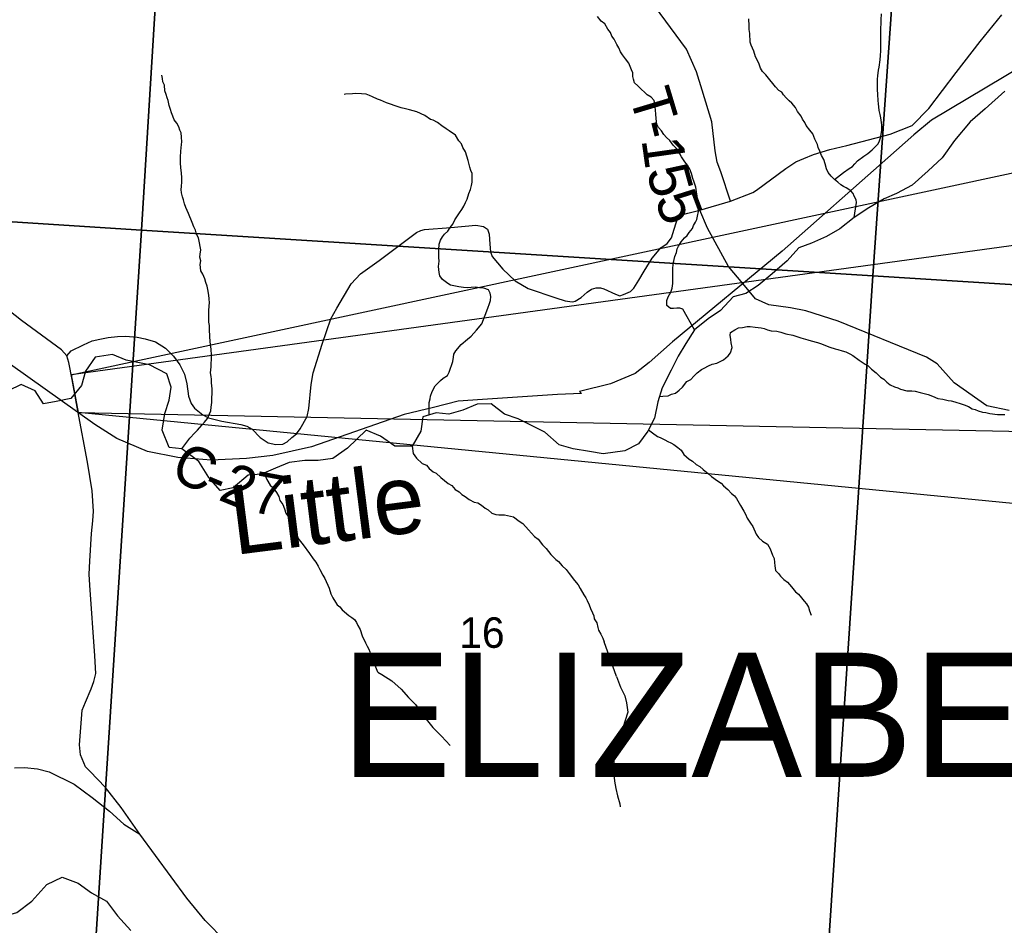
# Model space of a CAD drawing. Extents: x 0 to 44, y -23.8 to 22.
# Drawn here: x 5.27 to 6.622, y 16.572 to 17.815 of the extents above; entities that cross this region are included whole.
import ezdxf

# ---------------------------------------------------------------- set-up
doc = ezdxf.new("R2010")
doc.units = 0
for name, color, linetype in [('Default', 7, 'Continuous'), ('GM_X_County_Road', 7, 'Continuous'), ('GM_X_County_Road_Text', 7, 'Continuous'), ('GM_X_Minor_River', 7, 'Continuous'), ('GM_X_Minor_River_Text', 7, 'Continuous'), ('GM_X_Rail_Line', 7, 'Continuous'), ('GM_X_Section', 7, 'Continuous'), ('GM_X_Section_Text', 7, 'Continuous'), ('GM_X_State_Route', 7, 'Continuous'), ('GM_X_Township_Road', 7, 'Continuous'), ('GM_X_Township_Road_Text', 7, 'Continuous'), ('GM_X_Township_Text', 7, 'Continuous'), ('SH_Data', 7, 'Continuous')]:
    doc.layers.add(name, color=color, linetype=linetype)

msp = doc.modelspace()

# ---------------------------------------------------------------- linework, layer by layer
at = {"layer": 'Default'}
msp.add_line((5.3413, 17.3275), (5.3505, 17.2755), dxfattribs=at)
at = {"layer": 'GM_X_County_Road'}
msp.add_line((6.204, 17.5534), (6.2464, 17.5658), dxfattribs=at)
for points in [[(6.2464, 17.5658), (6.2769, 17.5775), (6.2822, 17.5808), (6.3221, 17.6107), (6.3361, 17.6195), (6.347, 17.6243), (6.3602, 17.6298), (6.3828, 17.6364), (6.4059, 17.6423), (6.4656, 17.6575), (6.4956, 17.6694), (6.5186, 17.6928), (6.5561, 17.7425), (6.5891, 17.785), (6.6186, 17.8214)], [(5.3353, 17.3535), (5.3413, 17.3604), (5.3582, 17.3685), (5.3701, 17.3739), (5.3805, 17.3765), (5.3918, 17.3785), (5.4047, 17.38), (5.416, 17.3805), (5.4316, 17.379), (5.4425, 17.3767), (5.4568, 17.3725), (5.4705, 17.364), (5.4814, 17.3528), (5.4904, 17.3411), (5.4969, 17.3285), (5.5001, 17.3148), (5.5024, 17.2981), (5.5057, 17.2881), (5.5106, 17.2814), (5.5218, 17.2726), (5.5297, 17.2682), (5.5481, 17.2638), (5.5742, 17.2591), (5.5821, 17.2568), (5.5894, 17.2527), (5.6005, 17.2415), (5.6114, 17.2342), (5.6219, 17.2316), (5.6316, 17.2322), (5.6377, 17.2354), (5.6439, 17.2412), (5.6503, 17.2465), (5.6553, 17.2533), (5.665, 17.2702), (5.6676, 17.2811), (5.6708, 17.3139), (5.6732, 17.3303), (5.6857, 17.3694), (5.6976, 17.404), (5.7058, 17.4188), (5.7256, 17.4524), (5.7381, 17.466), (5.7639, 17.4844), (5.8151, 17.5229), (5.8213, 17.5254), (5.826, 17.527), (5.8625, 17.5296), (5.8967, 17.5327), (5.9074, 17.5309), (5.9125, 17.5273), (5.9151, 17.5205), (5.9157, 17.5065), (5.9167, 17.4962), (5.919, 17.4899), (5.9338, 17.4726), (5.9506, 17.4565), (5.9683, 17.4459), (6.0063, 17.4332), (6.0193, 17.4289), (6.0255, 17.4278), (6.0298, 17.4274), (6.0331, 17.4283), (6.0413, 17.4337), (6.0494, 17.4407), (6.0553, 17.4449), (6.0617, 17.4466), (6.068, 17.4467), (6.0722, 17.4456), (6.0886, 17.438), (6.0945, 17.436), (6.0995, 17.4374), (6.1091, 17.4416), (6.1138, 17.4461), (6.1204, 17.4571), (6.1276, 17.4697), (6.1388, 17.4876), (6.1507, 17.5015), (6.1594, 17.5077), (6.1651, 17.5155), (6.1688, 17.5274), (6.1738, 17.5431), (6.1791, 17.5471), (6.1876, 17.5491), (6.204, 17.5534)], [(5.2631, 16.7882), (5.2772, 16.7884), (5.295, 16.7867), (5.3109, 16.7827), (5.3454, 16.7655), (5.3698, 16.7471), (5.3938, 16.7284), (5.4134, 16.7109), (5.4353, 16.6969)]]:
    msp.add_lwpolyline(points, dxfattribs=at)
at = {"layer": 'GM_X_Minor_River'}
for points in [[(6.1968, 17.3893), (6.1969, 17.389), (6.1807, 17.4174), (6.1766, 17.419), (6.1724, 17.419), (6.1682, 17.4183), (6.164, 17.4184), (6.1591, 17.4226), (6.1588, 17.4294), (6.1608, 17.4344), (6.1643, 17.4408), (6.1663, 17.4464), (6.1671, 17.4529), (6.1672, 17.4605), (6.1669, 17.4654), (6.167, 17.4742), (6.1682, 17.4814), (6.1698, 17.4897), (6.1721, 17.4954), (6.1729, 17.5003), (6.1749, 17.5041), (6.1787, 17.5097), (6.183, 17.5154), (6.1868, 17.5184), (6.1895, 17.5229), (6.1941, 17.5282), (6.1957, 17.5323), (6.1984, 17.5368), (6.2, 17.5406), (6.2012, 17.5452), (6.2024, 17.5516), (6.202, 17.5569), (6.2014, 17.5626), (6.201, 17.568), (6.2007, 17.5729), (6.1996, 17.5786), (6.1986, 17.5847), (6.196, 17.5931), (6.1945, 17.5969), (6.1927, 17.6038), (6.1905, 17.6095), (6.1872, 17.6149), (6.1838, 17.6199), (6.179, 17.6264), (6.1767, 17.6306), (6.1715, 17.6386), (6.1674, 17.6425), (6.1629, 17.649), (6.1584, 17.6532), (6.1546, 17.6571), (6.1517, 17.6621), (6.1475, 17.6667), (6.1453, 17.6709), (6.1446, 17.6751), (6.1443, 17.6792), (6.1436, 17.6853), (6.1433, 17.6907), (6.1429, 17.6952), (6.1426, 17.6998), (6.1415, 17.704), (6.1374, 17.7082), (6.1321, 17.7117), (6.1284, 17.7152), (6.1243, 17.719), (6.119, 17.724), (6.1145, 17.7283), (6.113, 17.7332), (6.1123, 17.737), (6.112, 17.742), (6.1105, 17.7458), (6.1087, 17.7504), (6.1065, 17.755), (6.102, 17.7611), (6.0982, 17.7665), (6.0953, 17.7707), (6.093, 17.776), (6.0904, 17.7806), (6.0864, 17.7879), (6.0834, 17.7921), (6.0815, 17.7971), (6.0778, 17.8017), (6.0737, 17.8089), (6.0688, 17.8128), (6.0636, 17.819)], [(6.3892, 17.5956), (6.3972, 17.6019), (6.4014, 17.6049), (6.4094, 17.6105), (6.414, 17.6131), (6.4171, 17.6169), (6.4206, 17.621), (6.4294, 17.6274), (6.4347, 17.6311), (6.4408, 17.636), (6.4454, 17.6405), (6.4489, 17.6446), (6.4508, 17.6484), (6.452, 17.6525), (6.4532, 17.6571), (6.454, 17.6631), (6.4541, 17.67), (6.4538, 17.6738), (6.4527, 17.6799), (6.4516, 17.6845), (6.4506, 17.6902), (6.4499, 17.6951), (6.4495, 17.6993), (6.4492, 17.7039), (6.4485, 17.7119), (6.4482, 17.7191), (6.4479, 17.7236), (6.448, 17.7331), (6.4485, 17.7377), (6.4497, 17.7457), (6.4505, 17.7498), (6.4517, 17.7597), (6.4522, 17.7654), (6.4526, 17.7718), (6.4529, 17.7965), (6.4526, 17.8041), (6.4531, 17.8087), (6.4531, 17.8144), (6.4536, 17.8227)], [(6.416, 17.5431), (6.4191, 17.5637), (6.4188, 17.5675), (6.4162, 17.5724), (6.4147, 17.5763), (6.4117, 17.5801), (6.4053, 17.584), (6.4016, 17.5859), (6.3978, 17.5883), (6.3937, 17.5917), (6.3892, 17.5956), (6.3847, 17.6002), (6.3805, 17.6052), (6.3783, 17.6102), (6.3761, 17.617), (6.3743, 17.6231), (6.3713, 17.6285), (6.3691, 17.6342), (6.3665, 17.6392), (6.3658, 17.6434), (6.3621, 17.651), (6.3591, 17.6583), (6.355, 17.6633), (6.3502, 17.6694), (6.3483, 17.6736), (6.345, 17.6782), (6.3431, 17.6824), (6.3382, 17.6886), (6.3357, 17.6943), (6.3304, 17.7004), (6.3267, 17.7035), (6.3229, 17.7074), (6.3192, 17.7116), (6.3166, 17.7154), (6.3128, 17.7178), (6.3079, 17.7228), (6.3042, 17.727), (6.3001, 17.7324), (6.2948, 17.7389), (6.2903, 17.7435), (6.2877, 17.7481), (6.2851, 17.755), (6.2807, 17.7638), (6.2781, 17.7714), (6.2748, 17.7798), (6.2733, 17.784), (6.2727, 17.7958), (6.272, 17.8011), (6.2721, 17.8064), (6.2714, 17.8159)], [(5.4931, 17.2256), (5.5041, 17.2406), (5.5107, 17.2477), (5.5145, 17.2515), (5.5207, 17.2582), (5.5241, 17.2624), (5.5284, 17.2676), (5.5311, 17.2737), (5.533, 17.2778), (5.5335, 17.2828), (5.5343, 17.2892), (5.5345, 17.3082), (5.5339, 17.3162), (5.5339, 17.3215), (5.5332, 17.3253), (5.5325, 17.3299), (5.5333, 17.3382), (5.5334, 17.3432), (5.5338, 17.3481), (5.5339, 17.3542), (5.5332, 17.3626), (5.5326, 17.3686), (5.5315, 17.3789), (5.5309, 17.3907), (5.531, 17.3949), (5.5303, 17.3998), (5.5299, 17.4044), (5.5301, 17.415), (5.5305, 17.4222), (5.5309, 17.426), (5.5306, 17.4317), (5.5303, 17.4367), (5.5289, 17.4443), (5.5278, 17.4489), (5.526, 17.4542), (5.5245, 17.4592), (5.5219, 17.4657), (5.5189, 17.4699), (5.5183, 17.479), (5.5191, 17.4836), (5.5176, 17.4889), (5.5181, 17.4931), (5.5189, 17.4988), (5.5182, 17.5033), (5.5175, 17.5087), (5.516, 17.5155), (5.5131, 17.5205), (5.5116, 17.5258), (5.5094, 17.5304), (5.5072, 17.5365), (5.502, 17.5487), (5.5002, 17.5529), (5.4987, 17.5568), (5.4969, 17.5621), (5.4954, 17.5674), (5.4939, 17.5716), (5.4925, 17.577), (5.4921, 17.5815), (5.4926, 17.5857), (5.493, 17.5922), (5.4931, 17.5983), (5.4928, 17.6043), (5.4917, 17.6119), (5.491, 17.6177), (5.4911, 17.626), (5.4916, 17.6344), (5.4925, 17.6435), (5.4929, 17.6473), (5.4926, 17.6537), (5.4919, 17.6594), (5.4904, 17.6633), (5.489, 17.6675), (5.486, 17.6728), (5.4826, 17.6774), (5.4808, 17.6824), (5.4789, 17.687), (5.4775, 17.6915), (5.4756, 17.6969), (5.4742, 17.7037), (5.4727, 17.7076), (5.4713, 17.7121), (5.4698, 17.7171), (5.4691, 17.7247), (5.4669, 17.7293), (5.4666, 17.7342), (5.4655, 17.7388)], [(5.8325, 17.2727), (5.8325, 17.2896), (5.8341, 17.2945), (5.8345, 17.2983), (5.8368, 17.3044), (5.8407, 17.3123), (5.8446, 17.316), (5.848, 17.3198), (5.8518, 17.3228), (5.8576, 17.3265), (5.8599, 17.331), (5.865, 17.3458), (5.8658, 17.3515), (5.8666, 17.3557), (5.8693, 17.3602), (5.8763, 17.3692), (5.8851, 17.3763), (5.8904, 17.3804), (5.8977, 17.3887), (5.9047, 17.3973), (5.9097, 17.4091), (5.9133, 17.4189), (5.9152, 17.4253), (5.9168, 17.4295), (5.9172, 17.4348), (5.9165, 17.4394), (5.9139, 17.444), (5.9075, 17.4463), (5.9018, 17.4468), (5.8962, 17.4476), (5.8901, 17.4473), (5.8848, 17.4466), (5.8795, 17.4471), (5.8734, 17.4483), (5.862, 17.4503), (5.8583, 17.4526), (5.8511, 17.4581), (5.8474, 17.4634), (5.8463, 17.4676), (5.8453, 17.476), (5.8461, 17.4832), (5.8458, 17.4885), (5.8459, 17.4988), (5.8464, 17.5067), (5.8483, 17.5124), (5.8507, 17.5166), (5.8537, 17.5203), (5.858, 17.5245), (5.8614, 17.5297), (5.8649, 17.5342), (5.868, 17.5399), (5.8742, 17.5497), (5.8773, 17.5542), (5.88, 17.5588), (5.8827, 17.5637), (5.8846, 17.5686), (5.887, 17.5761), (5.8894, 17.5818), (5.8906, 17.5871), (5.8917, 17.592), (5.8918, 17.5996), (5.8915, 17.6038), (5.89, 17.6076), (5.8886, 17.6122), (5.886, 17.6214), (5.8827, 17.6332), (5.879, 17.6393), (5.8768, 17.6443), (5.8734, 17.6485), (5.8686, 17.6562), (5.8599, 17.662), (5.8558, 17.6651), (5.8502, 17.6693), (5.8441, 17.6736), (5.8381, 17.6767), (5.8343, 17.6779), (5.8268, 17.6833), (5.8158, 17.6884), (5.8056, 17.6912), (5.8003, 17.6924), (5.7943, 17.694), (5.786, 17.6967), (5.7795, 17.6987), (5.7739, 17.7007), (5.7697, 17.7023), (5.7656, 17.7042), (5.7618, 17.7058), (5.7546, 17.7089), (5.7508, 17.7105), (5.7463, 17.7124), (5.7399, 17.7129), (5.7312, 17.7134), (5.7274, 17.713), (5.7175, 17.7124), (5.7157, 17.7123)], [(6.6227, 17.7167), (6.596, 17.6925), (6.5754, 17.6744), (6.5536, 17.6491), (6.5368, 17.6252), (6.5177, 17.6071), (6.4959, 17.5875), (6.4742, 17.5762), (6.4571, 17.5687), (6.4362, 17.5567), (6.416, 17.5431), (6.3965, 17.5276), (6.3783, 17.5171), (6.3577, 17.5081), (6.3403, 17.5017), (6.3242, 17.4836)], [(6.3242, 17.4836), (6.3036, 17.4659), (6.2845, 17.45), (6.2674, 17.4391), (6.2499, 17.4342), (6.2327, 17.4157), (6.2156, 17.404), (6.1969, 17.389), (6.185, 17.3704), (6.1743, 17.353), (6.1647, 17.3337), (6.1524, 17.3095), (6.1466, 17.2901), (6.1419, 17.2681), (6.133, 17.2499), (6.12, 17.2325), (6.1014, 17.2232), (6.0714, 17.2188), (6.0528, 17.2223), (6.0305, 17.2258), (6.0112, 17.2312), (5.9916, 17.2488), (5.9723, 17.2584), (5.9549, 17.2672), (5.936, 17.2734), (5.9179, 17.2875), (5.8986, 17.2873), (5.8788, 17.279), (5.8594, 17.2734), (5.842, 17.2754), (5.8241, 17.2698), (5.8213, 17.2501), (5.8091, 17.2296), (5.7855, 17.2294), (5.7659, 17.2431), (5.7462, 17.2516), (5.7207, 17.2267), (5.7005, 17.2124), (5.6804, 17.2098), (5.6618, 17.2099), (5.6402, 17.207), (5.6215, 17.1991), (5.6025, 17.1912), (5.5843, 17.1898), (5.5637, 17.1721), (5.5455, 17.1688), (5.53, 17.1863), (5.5162, 17.2084), (5.4931, 17.2256), (5.4757, 17.2276), (5.466, 17.2516), (5.4696, 17.2743), (5.4758, 17.2925), (5.4782, 17.3104), (5.4726, 17.3286), (5.4488, 17.3409), (5.4166, 17.3475), (5.3977, 17.3552), (5.3742, 17.3515), (5.3608, 17.3326), (5.3553, 17.3125), (5.3408, 17.2947), (5.3203, 17.2907), (5.3032, 17.2877), (5.2919, 17.3053), (5.2723, 17.3141), (5.2544, 17.3055)], [(6.1491, 17.2976), (6.1535, 17.2981), (6.1608, 17.2987), (6.1653, 17.3009), (6.1707, 17.3024), (6.176, 17.3065), (6.1802, 17.3106), (6.1864, 17.3181), (6.1917, 17.3211), (6.196, 17.3256), (6.2006, 17.3301), (6.2063, 17.3346), (6.2101, 17.3365), (6.2159, 17.3398), (6.2212, 17.342), (6.2273, 17.3435), (6.233, 17.3461), (6.2368, 17.3479), (6.2433, 17.3535), (6.2464, 17.3577), (6.2484, 17.3649), (6.2473, 17.3713), (6.2466, 17.3759), (6.2459, 17.3816), (6.2464, 17.3854), (6.2521, 17.3891), (6.2574, 17.3917), (6.2627, 17.3924), (6.2692, 17.3935), (6.2734, 17.3938), (6.2802, 17.3929), (6.2882, 17.3917), (6.2923, 17.3909), (6.2969, 17.3893), (6.3022, 17.3877), (6.3097, 17.3872), (6.3154, 17.386), (6.3222, 17.3837), (6.3317, 17.3816), (6.3389, 17.3797), (6.343, 17.3781), (6.3525, 17.3753), (6.357, 17.3741), (6.3657, 17.3717), (6.371, 17.3701), (6.3767, 17.3674), (6.3827, 17.3654), (6.3899, 17.3631), (6.3937, 17.3622), (6.3997, 17.3603), (6.4046, 17.3591), (6.4103, 17.3563), (6.4141, 17.354), (6.4231, 17.3474), (6.431, 17.342), (6.4348, 17.3401), (6.44, 17.3351), (6.4464, 17.33), (6.4524, 17.3243), (6.4569, 17.3215), (6.4607, 17.3173), (6.4656, 17.3138), (6.4716, 17.3107), (6.4758, 17.3095), (6.4799, 17.3076), (6.4886, 17.3056), (6.4951, 17.3055), (6.5, 17.305), (6.5068, 17.3031), (6.5178, 17.3003), (6.5238, 17.2979), (6.531, 17.2951), (6.5378, 17.2939), (6.545, 17.2923), (6.5492, 17.2919), (6.5541, 17.2903), (6.5631, 17.2875), (6.5673, 17.2863), (6.573, 17.284), (6.5782, 17.2809), (6.5824, 17.2797), (6.5862, 17.2781), (6.5922, 17.2761), (6.5968, 17.2757), (6.6021, 17.2741), (6.6127, 17.2728), (6.6229, 17.2727)], [(6.1335, 17.2517), (6.1393, 17.2477), (6.1461, 17.2427), (6.1499, 17.2415), (6.1563, 17.238), (6.1604, 17.2357), (6.1646, 17.2341), (6.1683, 17.2318), (6.174, 17.2275), (6.1785, 17.224), (6.1822, 17.2179), (6.1897, 17.2117), (6.1942, 17.209), (6.1991, 17.2044), (6.2044, 17.2017), (6.2089, 17.1974), (6.216, 17.1913), (6.2202, 17.1878), (6.2285, 17.182), (6.2334, 17.1789), (6.2367, 17.175), (6.2424, 17.17), (6.2476, 17.1643), (6.2517, 17.1615), (6.2547, 17.1577), (6.2599, 17.1481), (6.2644, 17.1401), (6.267, 17.1363), (6.2692, 17.1305), (6.2737, 17.1236), (6.277, 17.1194), (6.2815, 17.1087), (6.2848, 17.1041), (6.2901, 17.0991), (6.2969, 17.0949), (6.3006, 17.0887), (6.3039, 17.08), (6.3061, 17.0754), (6.3068, 17.0697), (6.3072, 17.0651), (6.3082, 17.059), (6.312, 17.0548), (6.315, 17.0509), (6.3195, 17.0463), (6.3247, 17.0428), (6.33, 17.0363), (6.3356, 17.0294), (6.3397, 17.0263), (6.3438, 17.0213), (6.3472, 17.0167), (6.3506, 17.0129), (6.3532, 17.0087), (6.3546, 17.0037), (6.357, 16.9976)], [(5.8091, 17.2296), (5.8108, 17.2192), (5.8153, 17.2131), (5.8232, 17.2058), (5.8288, 17.2034), (5.8326, 17.1988), (5.8382, 17.1942), (5.842, 17.1922), (5.8488, 17.1864), (5.8585, 17.1783), (5.8638, 17.1756), (5.8683, 17.1698), (5.8736, 17.1667), (5.8773, 17.1633), (5.8818, 17.1602), (5.8875, 17.1563), (5.8946, 17.1528), (5.8992, 17.1516), (5.9045, 17.1485), (5.9097, 17.1446), (5.9135, 17.1419), (5.9188, 17.1377), (5.924, 17.1357), (5.9282, 17.1353), (5.9358, 17.1352), (5.9483, 17.1327), (5.9562, 17.1266), (5.9611, 17.1234), (5.9689, 17.1146), (5.9772, 17.1054), (5.9821, 17.1019), (5.9884, 17.0942), (5.9933, 17.0892), (5.9997, 17.0808), (6.0064, 17.0739), (6.0102, 17.0712), (6.0154, 17.0654), (6.0207, 17.06), (6.0248, 17.0546), (6.0323, 17.045), (6.0371, 17.0393), (6.0401, 17.0343), (6.0449, 17.0255), (6.0475, 17.0213), (6.0494, 17.0175), (6.0524, 17.0117), (6.0542, 17.0068), (6.0568, 17.0007), (6.0586, 16.9964), (6.0593, 16.9926), (6.0627, 16.9869), (6.0641, 16.9808), (6.0652, 16.977), (6.0682, 16.9713), (6.0708, 16.9659), (6.0728, 16.9608)], [(5.6061, 17.1925), (5.6097, 17.1838), (5.6142, 17.1761), (5.6179, 17.1726), (5.6228, 17.1657), (5.6261, 17.1604), (5.6276, 17.155), (5.6317, 17.1493), (5.6339, 17.1436), (5.6357, 17.1375), (5.6406, 17.1313), (5.6428, 17.1241), (5.6458, 17.1199), (5.648, 17.1122), (5.6506, 17.1073), (5.6543, 17.1008), (5.6595, 17.0939), (5.6685, 17.0823), (5.6733, 17.0747), (5.6771, 17.0701), (5.6804, 17.0647), (5.6826, 17.0601), (5.6867, 17.0525), (5.6893, 17.0479), (5.6912, 17.0437), (5.6934, 17.0387), (5.6953, 17.0345), (5.6974, 17.0269), (5.7004, 17.0215), (5.7041, 17.0154), (5.7064, 17.0116), (5.7101, 17.0089), (5.7131, 17.005), (5.7221, 16.9973), (5.7263, 16.9942), (5.73, 16.9915), (5.7326, 16.9873), (5.7345, 16.9835), (5.7378, 16.9777), (5.7404, 16.9693), (5.7452, 16.9594), (5.7474, 16.9552), (5.7497, 16.951), (5.7511, 16.9472), (5.7518, 16.9455)], [(6.0899, 16.9133), (6.0728, 16.9608)], [(5.7619, 16.9195), (5.762, 16.9192), (5.7518, 16.9455)], [(5.762, 16.9192), (5.7678, 16.9162), (5.7814, 16.9075), (5.7942, 16.8961), (5.8044, 16.8844), (5.8139, 16.8749), (5.8249, 16.8593), (5.8377, 16.8434), (5.8494, 16.8317), (5.8613, 16.8187)], [(6.0899, 16.9133), (6.0951, 16.8989), (6.1012, 16.8868), (6.1034, 16.8773), (6.1053, 16.8644)], [(6.1053, 16.8644), (6.0986, 16.8431), (6.097, 16.8329), (6.0913, 16.823), (6.0879, 16.8132), (6.086, 16.8033), (6.0863, 16.7901), (6.0863, 16.7794), (6.087, 16.7696), (6.0889, 16.7597), (6.0911, 16.7498), (6.0945, 16.7388), (6.0949, 16.7347)], [(5.1407, 16.5676), (5.1623, 16.574), (5.1808, 16.5725), (5.2009, 16.5736), (5.2259, 16.5797), (5.2463, 16.5834), (5.2664, 16.5895), (5.2869, 16.6051), (5.3077, 16.6279), (5.3286, 16.6381), (5.3505, 16.6297), (5.369, 16.6164), (5.3898, 16.605), (5.4046, 16.5848), (5.4231, 16.5646)]]:
    msp.add_lwpolyline(points, dxfattribs=at)
at = {"layer": 'GM_X_Rail_Line'}
msp.add_lwpolyline([(7.045, 17.9889), (6.5222, 17.6767), (6.4979, 17.6566), (6.4625, 17.6252), (6.317, 17.4973), (6.1665, 17.3727), (6.1347, 17.3442), (6.1154, 17.3292), (6.0817, 17.3151), (6.0391, 17.3045), (6.0419, 17.3018), (6.0089, 17.3002), (5.9059, 17.2937), (5.8722, 17.2913), (5.8384, 17.2825), (5.7982, 17.2728), (5.6711, 17.2286), (5.618, 17.2165), (5.5818, 17.2125), (5.5335, 17.2101), (5.4877, 17.2141), (5.4459, 17.2221), (5.404, 17.2398), (5.3735, 17.2591), (5.121, 17.4386)], dxfattribs=at)
at = {"layer": 'GM_X_Section'}
for points in [[(4.4853, 18.6191), (5.5009, 18.5537), (5.4377, 17.5257), (4.437, 17.5902)], [(5.5009, 18.5537), (6.5134, 18.488), (6.4419, 17.4633), (5.4377, 17.5257)], [(6.5134, 18.488), (7.5123, 18.4238), (7.4446, 17.3999), (6.4419, 17.4633)], [(4.437, 17.5902), (5.4377, 17.5257), (5.3718, 16.5024), (4.3733, 16.5584)], [(5.4377, 17.5257), (6.4419, 17.4633), (6.3745, 16.447), (5.3718, 16.5024)], [(6.4419, 17.4633), (7.4446, 17.3999), (7.376, 16.3855), (6.3745, 16.447)]]:
    msp.add_lwpolyline(points, close=True, dxfattribs=at)
at = {"layer": 'GM_X_State_Route'}
msp.add_lwpolyline([(5.553, 16.55), (5.5249, 16.5786), (5.4998, 16.609), (5.4353, 16.6969), (5.4098, 16.7338), (5.3884, 16.7609), (5.3668, 16.7833), (5.361, 16.7893), (5.3539, 16.8059), (5.3527, 16.8197), (5.3543, 16.8434), (5.3564, 16.867), (5.3607, 16.8781), (5.3685, 16.8963), (5.3723, 16.9066), (5.3748, 16.9175), (5.3738, 16.9417), (5.3667, 17.0386), (5.366, 17.0539), (5.3667, 17.0717), (5.3688, 17.1097), (5.3709, 17.1268), (5.3719, 17.1404), (5.3698, 17.1682), (5.3635, 17.2076), (5.3501, 17.2779), (5.3426, 17.321), (5.3379, 17.3442), (5.3353, 17.3535), (5.328, 17.3617), (5.2731, 17.402), (5.2489, 17.4205)], dxfattribs=at)
at = {"layer": 'GM_X_Township_Road'}
msp.add_line((6.204, 17.5534), (6.2464, 17.5658), dxfattribs=at)
for points in [[(6.2073, 17.7179), (6.1995, 17.7431), (6.1861, 17.7744), (6.085, 17.9112), (6.0188, 18.0021), (5.8865, 18.1427), (5.7431, 18.3026), (5.6246, 18.4101), (5.5308, 18.5011), (5.4316, 18.6252)], [(6.2464, 17.5658), (6.233, 17.6059), (6.2279, 17.6193), (6.2252, 17.6349), (6.2207, 17.6748), (6.2073, 17.7179)], [(6.629, 17.2783), (6.5981, 17.2847), (6.5532, 17.3165), (6.5301, 17.3424), (6.5156, 17.3516), (6.394, 17.401), (6.3495, 17.4154), (6.3285, 17.4191), (6.2989, 17.4233), (6.2804, 17.4315), (6.2631, 17.4525), (6.2437, 17.476), (6.2149, 17.5287), (6.204, 17.5534)]]:
    msp.add_lwpolyline(points, dxfattribs=at)
at = {"layer": 'SH_Data'}
for points in [[(5.3413, 17.3275), (9.7799, 18.2797), (9.7799, 17.9369)], [(5.3505, 17.2755), (9.7548, 17.1872), (9.7548, 16.8468)]]:
    msp.add_lwpolyline(points, close=True, dxfattribs=at)

# ---------------------------------------------------------------- texts
at = {"layer": 'GM_X_County_Road_Text'}
for s, rotation, p in [('C', 335.5073, (5.475, 17.1858)), ('2', 337.9096, (5.5414, 17.1564)), ('7', 349.5085, (5.5858, 17.1398)), ('-', 337.3378, (5.5192, 17.1657))]:
    msp.add_text(s, height=0.0568, rotation=rotation, dxfattribs=at).set_placement(p)
at = {"layer": 'GM_X_Minor_River_Text'}
msp.add_text('Little', height=0.09469, rotation=7.2298, dxfattribs=at).set_placement((5.5653, 17.08))
at = {"layer": 'GM_X_Section_Text'}
msp.add_text('16', height=0.04186, rotation=0, dxfattribs=at).set_placement((5.8739, 16.9527))
at = {"layer": 'GM_X_Township_Road_Text'}
for s, rotation, p in [('T', 286.7366, (6.1067, 17.7112)), ('-', 283.7617, (6.1187, 17.6713)), ('1', 277.9826, (6.124, 17.6501)), ('5', 285.466, (6.1305, 17.6075)), ('5', 290.722, (6.1416, 17.5684))]:
    msp.add_text(s, height=0.0568, rotation=rotation, dxfattribs=at).set_placement(p)
at = {"layer": 'GM_X_Township_Text'}
msp.add_text('ELIZABETH', height=0.17045, rotation=0, dxfattribs=at).set_placement((5.7113, 16.7756))

doc.saveas('drawing.dxf')
